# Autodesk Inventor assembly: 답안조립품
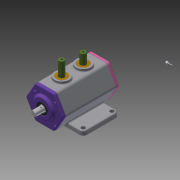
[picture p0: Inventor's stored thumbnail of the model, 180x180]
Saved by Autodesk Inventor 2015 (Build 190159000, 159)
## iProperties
Created: 2021-06
Part Number: 답안조립품
Document SubType Name: Assembly
Designer: now
Author: now
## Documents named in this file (11)
- C:\Users\now\Desktop\710606V1028\답안조립품.iam
- C:\Users\now\Desktop\710606V1028\뒷커버.ipt
- C:\Users\now\Desktop\710606V1028\베어링 6203.ipt
- C:\Users\now\Desktop\710606V1028\베어링 6302.ipt
- C:\Users\now\Desktop\710606V1028\본체.ipt
- C:\Users\now\Desktop\710606V1028\볼트 M4.ipt
- C:\Users\now\Desktop\710606V1028\부시.ipt
- C:\Users\now\Desktop\710606V1028\슬라이더.ipt
- C:\Users\now\Desktop\710606V1028\앞커버.ipt
- C:\Users\now\Desktop\710606V1028\오일실.ipt
- C:\Users\now\Desktop\710606V1028\편심축.ipt
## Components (3 placed, 3 different names)
1. 7-베어링 6203:1
2. 9-M4-소켓머리:1
3. 8-오일실:1
